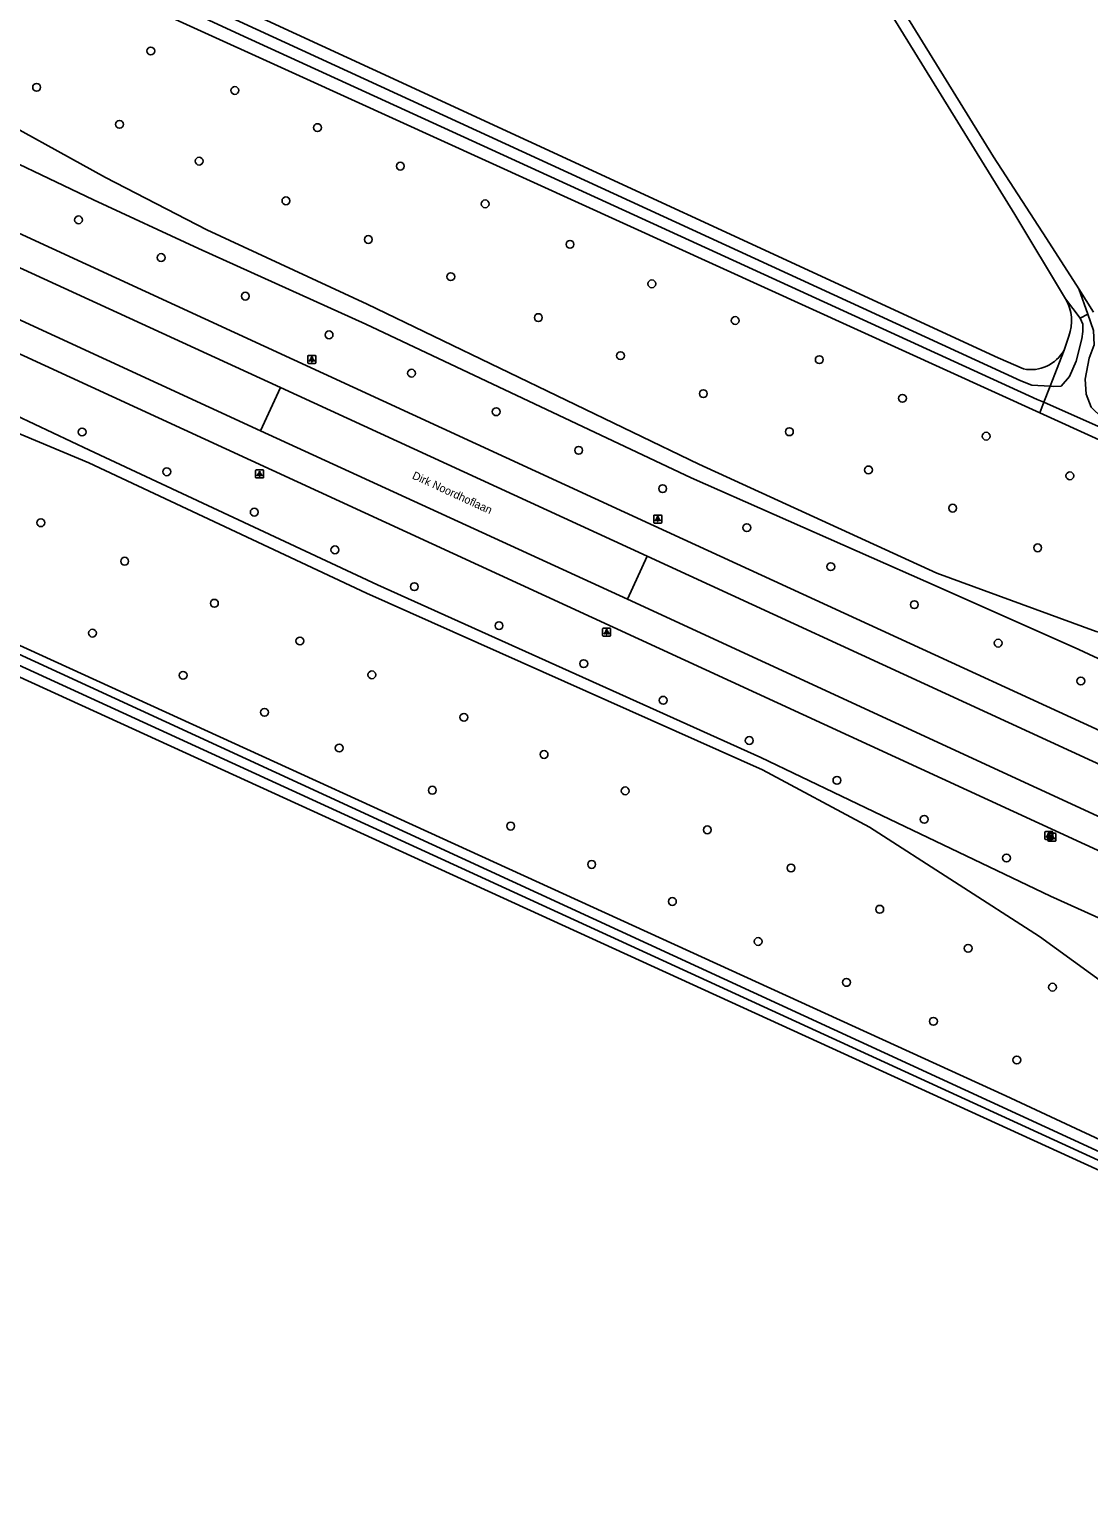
# Model space of a CAD drawing. Extents: x 155209 to 156823, y 385356 to 388482.
# Drawn here: x 155450 to 155582.4, y 387477 to 387660.8 of the extents above; entities that cross this region are included whole.
import ezdxf

# ---------------------------------------------------------------- set-up
doc = ezdxf.new("R2010")
doc.units = 0
for name, color, linetype in [('IMGEO_Berm_open', 7, 'Continuous'), ('IMGEO_Boom', 7, 'Continuous'), ('IMGEO_Bouwland', 7, 'Continuous'), ('IMGEO_Groenvoorziening', 7, 'Continuous'), ('IMGEO_Lichtpunt', 7, 'Continuous'), ('IMGEO_Oever', 7, 'Continuous'), ('IMGEO_Openbare_ruimte_label', 7, 'Continuous'), ('IMGEO_Rijbaan_lokaal_gesloten', 7, 'Continuous'), ('IMGEO_Waterloop', 7, 'Continuous')]:
    doc.layers.add(name, color=color, linetype=linetype)

msp = doc.modelspace()

# ---------------------------------------------------------------- linework, layer by layer
at = {"layer": 'IMGEO_Berm_open'}
for points in [[(155481.37, 387616.06), (155478.91, 387610.65)], [(155527.21, 387594.99), (155524.74, 387589.61)]]:
    msp.add_lwpolyline(points, dxfattribs=at)
at = {"layer": 'IMGEO_Boom'}
for centre in [(155465.18, 387658.1), (155450.91, 387653.56), (155475.69, 387653.17), (155461.27, 387648.93), (155486.01, 387648.53), (155471.22, 387644.34), (155496.36, 387643.71), (155482.07, 387639.38), (155506.97, 387639), (155456.15, 387637), (155492.36, 387634.55), (155517.57, 387633.94), (155466.47, 387632.29), (155502.67, 387629.9), (155527.8, 387629.01), (155476.99, 387627.47), (155513.62, 387624.79), (155538.22, 387624.42), (155487.46, 387622.63), (155523.88, 387620.03), (155548.72, 387619.54), (155497.77, 387617.84), (155534.24, 387615.29), (155559.12, 387614.71), (155508.35, 387613.03), (155456.6, 387610.49), (155544.99, 387610.53), (155569.58, 387609.97), (155518.66, 387608.21), (155467.18, 387605.53), (155554.87, 387605.76), (155580.04, 387605.02), (155529.15, 387603.42), (155478.11, 387600.48), (155565.4, 387600.98), (155451.44, 387599.16), (155539.67, 387598.55), (155488.19, 387595.77), (155576.02, 387596.03), (155461.92, 387594.35), (155550.16, 387593.67), (155498.11, 387591.17), (155473.13, 387589.1), (155560.61, 387588.93), (155508.69, 387586.3), (155457.89, 387585.37), (155483.81, 387584.39), (155571.08, 387584.12), (155519.29, 387581.56), (155469.22, 387580.1), (155492.81, 387580.16), (155581.41, 387579.38), (155529.22, 387576.98), (155479.39, 387575.48), (155504.31, 387574.85), (155488.73, 387571.01), (155539.97, 387571.95), (155514.33, 387570.21), (155500.36, 387565.74), (155524.47, 387565.66), (155550.93, 387566.98), (155561.84, 387562.1), (155510.15, 387561.26), (155534.74, 387560.79), (155520.28, 387556.47), (155572.12, 387557.28), (155545.19, 387556.03), (155530.37, 387551.84), (155556.28, 387550.87), (155541.08, 387546.84), (155567.33, 387545.99), (155552.12, 387541.73), (155577.87, 387541.13), (155562.99, 387536.87), (155573.41, 387532.04)]:
    msp.add_circle(centre, 0.489, dxfattribs=at)
at = {"layer": 'IMGEO_Bouwland'}
for points in [[(155384.77, 387699.96), (155484.23, 387654.8), (155576.27, 387612.9)], [(155574.25, 387618.39), (155571.1, 387619.78), (155492.9, 387655.83), (155427.92, 387685.79)], [(155366.18, 387677.47), (155366.51, 387676.93), (155371.66, 387676.2), (155392.8, 387671.57), (155407.11, 387668.5), (155416.96, 387665.11), (155430.67, 387658.41), (155443.17, 387651.3), (155459.51, 387642.3), (155472.17, 387635.77), (155492.21, 387626.46), (155533.66, 387606.49), (155563.42, 387592.86), (155583.32, 387585.58), (155602.84, 387580.68), (155613.17, 387577.54), (155623.19, 387574.28), (155630.52, 387570.85), (155637.04, 387566.92), (155643.66, 387562.28), (155654.51, 387556.89), (155655.59, 387555.59)], [(155638.8, 387518.44), (155636.75, 387517.59), (155633.49, 387518.29), (155628.37, 387520.11), (155614.39, 387525.22), (155604.76, 387528.61), (155593.3, 387535.81), (155584.75, 387541.29), (155576.23, 387547.46), (155555.02, 387561.13), (155541.61, 387568.3), (155492.15, 387590.36), (155457.45, 387606.65), (155444.55, 387612), (155409.96, 387624.12), (155401.32, 387627.3), (155395.62, 387629.27), (155393.71, 387629.22), (155391.65, 387627.8), (155387.43, 387615.91), (155385.51, 387611.21), (155384.83, 387609.49)], [(155582.99, 387625.47), (155581.17, 387628.37)], [(155579.9, 387622.46), (155579.31, 387620.72)], [(155576.27, 387612.9), (155683.29, 387564.19), (155687.39, 387562.46), (155687.85, 387563.57), (155688.41, 387564.9)], [(155387.83, 387608.06), (155388.99, 387611.34), (155404.91, 387603.85), (155572.02, 387527.55), (155670.99, 387481.41), (155675.14, 387479.3)], [(155675.14, 387479.3), (155674.79, 387478.07), (155674.48, 387476.99), (155672.26, 387477.78), (155393.15, 387605.27), (155387.83, 387608.06)]]:
    msp.add_lwpolyline(points, dxfattribs=at)
for centre, radius, start, end in [((155574.96, 387624.39), 5.3, 338.7189, 31.1559), ((155575.18, 387623.03), 4.74, 258.6778, 330.7072)]:
    msp.add_arc(centre, radius, start, end, dxfattribs=at)
at = {"layer": 'IMGEO_Groenvoorziening'}
for points in [[(155613.36, 387568.6), (155600.55, 387574.49), (155584.82, 387581.6), (155581.15, 387583.34), (155563.84, 387591.01), (155532.71, 387604.77), (155492.04, 387623.95), (155471.14, 387633.43), (155458.04, 387639.49), (155442.12, 387647.09), (155430.62, 387652.37), (155421.79, 387656.19), (155412.68, 387659.27)], [(155393.21, 387636.15), (155398.2, 387635.3), (155404.64, 387632.33), (155446.04, 387613.65), (155457.54, 387608.21), (155493.51, 387591.42), (155541.42, 387569.85), (155556.55, 387562.59), (155577.64, 387552.52), (155592.12, 387545.97), (155596.02, 387544.23), (155603.92, 387540.66), (155609.57, 387538.12), (155614.96, 387536.45), (155620.18, 387536.16), (155628.18, 387534.46), (155634.08, 387532.62), (155645.27, 387528.8), (155650.36, 387528.34), (155652.21, 387528.56), (155638.8, 387518.44)]]:
    msp.add_lwpolyline(points, dxfattribs=at)
at = {"layer": 'IMGEO_Lichtpunt'}
for p, q in [((155484.81, 387619.97), (155484.81, 387619.16)), ((155484.81, 387619.97), (155484.81, 387619.16)), ((155485.71, 387620.07), (155484.91, 387620.07)), ((155485.71, 387620.07), (155484.91, 387620.07)), ((155485.81, 387619.16), (155485.81, 387619.97)), ((155485.81, 387619.16), (155485.81, 387619.97)), ((155484.91, 387619.07), (155485.71, 387619.07)), ((155484.91, 387619.07), (155485.71, 387619.07)), ((155478.28, 387605.66), (155478.28, 387604.85)), ((155478.28, 387605.66), (155478.28, 387604.85)), ((155479.18, 387605.76), (155478.38, 387605.76)), ((155479.18, 387605.76), (155478.38, 387605.76)), ((155478.38, 387604.76), (155479.18, 387604.76)), ((155478.38, 387604.76), (155479.18, 387604.76)), ((155479.28, 387604.85), (155479.28, 387605.66)), ((155479.28, 387604.85), (155479.28, 387605.66)), ((155528.04, 387600.03), (155528.04, 387599.22)), ((155528.04, 387600.03), (155528.04, 387599.22)), ((155528.94, 387600.12), (155528.13, 387600.12)), ((155528.94, 387600.12), (155528.13, 387600.12)), ((155528.13, 387599.12), (155528.94, 387599.12)), ((155528.13, 387599.12), (155528.94, 387599.12)), ((155529.03, 387599.22), (155529.03, 387600.03)), ((155529.03, 387599.22), (155529.03, 387600.03)), ((155521.65, 387585.9), (155521.65, 387585.09)), ((155521.65, 387585.9), (155521.65, 387585.09)), ((155522.55, 387585.99), (155521.75, 387585.99)), ((155522.55, 387585.99), (155521.75, 387585.99)), ((155521.75, 387585), (155522.55, 387585)), ((155521.75, 387585), (155522.55, 387585)), ((155522.65, 387585.09), (155522.65, 387585.9)), ((155522.65, 387585.09), (155522.65, 387585.9)), ((155576.91, 387560.49), (155576.91, 387559.69)), ((155576.91, 387560.49), (155576.91, 387559.69)), ((155577.81, 387560.59), (155577, 387560.59)), ((155577.81, 387560.59), (155577, 387560.59)), ((155577.91, 387559.69), (155577.91, 387560.49)), ((155577.91, 387559.69), (155577.91, 387560.49)), ((155577, 387559.59), (155577.81, 387559.59)), ((155577, 387559.59), (155577.81, 387559.59)), ((155577.3, 387560.28), (155577.3, 387559.48)), ((155577.3, 387560.28), (155577.3, 387559.48)), ((155578.2, 387560.38), (155577.39, 387560.38)), ((155578.2, 387560.38), (155577.39, 387560.38)), ((155577.39, 387559.38), (155578.2, 387559.38)), ((155577.39, 387559.38), (155578.2, 387559.38)), ((155578.3, 387559.48), (155578.3, 387560.28)), ((155578.3, 387559.48), (155578.3, 387560.28))]:
    msp.add_line(p, q, dxfattribs=at)
for points in [[(155485.19, 387619.63), (155485.22, 387619.61), (155485.04, 387619.34), (155485, 387619.37), (155485.19, 387619.63)], [(155485.29, 387619.59), (155485.34, 387619.59), (155485.34, 387619.26), (155485.29, 387619.26), (155485.29, 387619.59)], [(155485.4, 387619.61), (155485.44, 387619.63), (155485.62, 387619.37), (155485.58, 387619.34), (155485.4, 387619.61)], [(155478.66, 387605.32), (155478.7, 387605.3), (155478.51, 387605.03), (155478.47, 387605.06), (155478.66, 387605.32)], [(155478.76, 387605.28), (155478.81, 387605.28), (155478.81, 387604.95), (155478.76, 387604.95), (155478.76, 387605.28)], [(155478.87, 387605.3), (155478.91, 387605.32), (155479.09, 387605.06), (155479.06, 387605.03), (155478.87, 387605.3)], [(155528.41, 387599.69), (155528.45, 387599.66), (155528.26, 387599.4), (155528.22, 387599.43), (155528.41, 387599.69)], [(155528.51, 387599.64), (155528.56, 387599.64), (155528.56, 387599.32), (155528.51, 387599.32), (155528.51, 387599.64)], [(155528.62, 387599.66), (155528.66, 387599.69), (155528.85, 387599.43), (155528.81, 387599.4), (155528.62, 387599.66)], [(155522.03, 387585.56), (155522.06, 387585.54), (155521.88, 387585.27), (155521.84, 387585.3), (155522.03, 387585.56)], [(155522.13, 387585.52), (155522.17, 387585.52), (155522.17, 387585.19), (155522.13, 387585.19), (155522.13, 387585.52)], [(155522.24, 387585.54), (155522.28, 387585.56), (155522.46, 387585.3), (155522.42, 387585.27), (155522.24, 387585.54)], [(155577.28, 387560.16), (155577.32, 387560.13), (155577.13, 387559.87), (155577.1, 387559.9), (155577.28, 387560.16)], [(155577.38, 387560.11), (155577.43, 387560.11), (155577.43, 387559.79), (155577.38, 387559.79), (155577.38, 387560.11)], [(155577.49, 387560.13), (155577.53, 387560.16), (155577.72, 387559.89), (155577.68, 387559.87), (155577.49, 387560.13)], [(155577.67, 387559.95), (155577.71, 387559.92), (155577.53, 387559.66), (155577.49, 387559.69), (155577.67, 387559.95)], [(155577.78, 387559.9), (155577.82, 387559.9), (155577.82, 387559.58), (155577.78, 387559.58), (155577.78, 387559.9)], [(155577.89, 387559.92), (155577.92, 387559.95), (155578.11, 387559.68), (155578.07, 387559.66), (155577.89, 387559.92)]]:
    msp.add_lwpolyline(points, dxfattribs=at)
for centre in [(155485.31, 387619.77), (155478.78, 387605.46), (155528.54, 387599.82), (155522.15, 387585.7), (155577.41, 387560.29), (155577.8, 387560.08)]:
    msp.add_circle(centre, 0.0994, dxfattribs=at)
for centre, start, end in [((155484.91, 387619.97), 90, 180), ((155484.91, 387619.97), 90, 180), ((155485.71, 387619.97), 0, 90), ((155485.71, 387619.97), 0, 90), ((155484.91, 387619.16), 180, 270), ((155484.91, 387619.16), 180, 270), ((155485.71, 387619.16), 270, 0), ((155485.71, 387619.16), 270, 360), ((155478.38, 387605.66), 90, 180), ((155478.38, 387605.66), 90, 180), ((155478.38, 387604.85), 180, 270), ((155478.38, 387604.85), 180, 270), ((155479.18, 387605.66), 0, 90), ((155479.18, 387605.66), 0, 90), ((155479.18, 387604.85), 270, 0), ((155479.18, 387604.85), 270, 360), ((155528.13, 387600.03), 90, 180), ((155528.13, 387600.03), 90, 180), ((155528.13, 387599.22), 180, 270), ((155528.13, 387599.22), 180, 270), ((155528.94, 387600.03), 0, 90), ((155528.94, 387600.03), 0, 90), ((155528.94, 387599.22), 270, 0), ((155528.94, 387599.22), 270, 360), ((155521.75, 387585.9), 90, 180), ((155521.75, 387585.9), 90, 180), ((155521.75, 387585.09), 180, 270), ((155521.75, 387585.09), 180, 270), ((155522.55, 387585.9), 0, 90), ((155522.55, 387585.9), 0, 90), ((155522.55, 387585.09), 270, 0), ((155522.55, 387585.09), 270, 360), ((155577, 387560.49), 90, 180), ((155577, 387560.49), 90, 180), ((155577.81, 387560.49), 0, 90), ((155577.81, 387560.49), 0, 90), ((155577, 387559.69), 180, 270), ((155577, 387559.69), 180, 270), ((155577.39, 387560.28), 90, 180), ((155577.39, 387560.28), 90, 180), ((155577.39, 387559.48), 180, 270), ((155577.39, 387559.48), 180, 270), ((155577.81, 387559.69), 270, 0), ((155577.81, 387559.69), 270, 360), ((155578.2, 387560.28), 0, 90), ((155578.2, 387560.28), 0, 90), ((155578.2, 387559.48), 270, 0), ((155578.2, 387559.48), 270, 360)]:
    msp.add_arc(centre, 0.0946, start, end, dxfattribs=at)
at = {"layer": 'IMGEO_Oever'}
for points in [[(155579.31, 387620.72), (155577.56, 387616.22)], [(155576.78, 387614.21), (155576.27, 387612.9)]]:
    msp.add_lwpolyline(points, dxfattribs=at)
at = {"layer": 'IMGEO_Rijbaan_lokaal_gesloten'}
for points in [[(155478.91, 387610.65), (155407.74, 387643.42)], [(155430.55, 387643.66), (155528.09, 387598.76), (155612.21, 387560.13)], [(155426.27, 387641.35), (155481.37, 387616.06)], [(155608.29, 387546.85), (155522.96, 387586.13), (155406.67, 387639.64)], [(155481.37, 387616.06), (155527.21, 387594.99)], [(155524.74, 387589.61), (155478.91, 387610.65)], [(155612.27, 387555.85), (155527.21, 387594.99)], [(155524.74, 387589.61), (155609.92, 387550.35)]]:
    msp.add_lwpolyline(points, dxfattribs=at)
at = {"layer": 'IMGEO_Waterloop'}
for points in [[(155579.5, 387627.13), (155573.16, 387637.67), (155547.63, 387679.07), (155514.23, 387733.53), (155490.25, 387772.25), (155480.51, 387787.87), (155464.43, 387814.8)], [(155465.7, 387815.6), (155481.79, 387788.65), (155491.53, 387773.04), (155515.51, 387734.32), (155548.91, 387679.86), (155570.49, 387644.86), (155577.11, 387634.68), (155581.17, 387628.37)], [(155577.56, 387616.22), (155575.29, 387616.34), (155573.93, 387616.87), (155429.47, 387683.31), (155426.98, 387684.45), (155388.58, 387702.11), (155387.58, 387700.55), (155450.97, 387671.91), (155476.31, 387660.15), (155518.63, 387640.78), (155575.97, 387614.57), (155576.78, 387614.21)], [(155581.32, 387624.73), (155579.5, 387627.13)], [(155581.17, 387628.37), (155582.3, 387625.23)], [(155576.78, 387614.21), (155583.63, 387611.17), (155687.3, 387563.36), (155687.43, 387563.76), (155687.62, 387564.31), (155584.11, 387612.23), (155582.69, 387613.6), (155582.08, 387615.21), (155581.95, 387617.1), (155582.47, 387619.71), (155583.06, 387621.39), (155583, 387623.17), (155582.3, 387625.23)], [(155582.3, 387625.23), (155581.32, 387624.73)], [(155577.56, 387616.22), (155577.98, 387616.2), (155578.95, 387616.22), (155580.01, 387617.45), (155580.82, 387619.33), (155581.52, 387622.15), (155581.66, 387623.07), (155581.65, 387623.98), (155581.32, 387624.73)], [(155577.56, 387616.22), (155576.78, 387614.21)], [(155390.96, 387609.31), (155389.83, 387609.71), (155389.41, 387608.65), (155392.18, 387607.27), (155673.22, 387478.41), (155674.2, 387478), (155674.39, 387478.09), (155674.45, 387478.23), (155674.56, 387478.53), (155674.43, 387478.76), (155673.1, 387479.4), (155390.96, 387609.31)]]:
    msp.add_lwpolyline(points, dxfattribs=at)

# ---------------------------------------------------------------- texts
at = {"layer": 'IMGEO_Openbare_ruimte_label'}
msp.add_text('Dirk Noordhoflaan', height=1, rotation=335.3569, dxfattribs=at).set_placement((155497.76, 387604.71))

doc.saveas('drawing.dxf')
